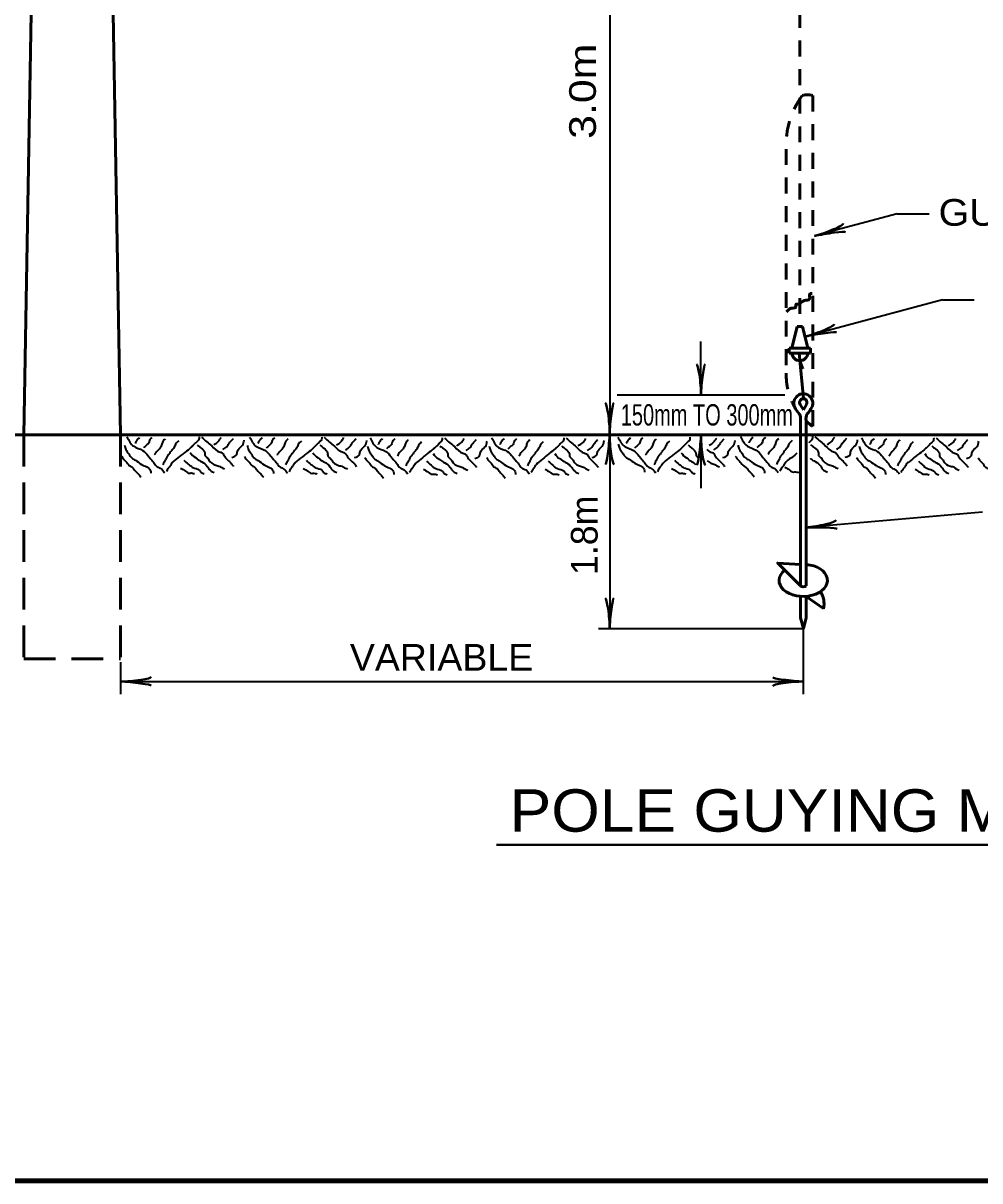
# Model space of a CAD drawing. Extents: x -34 to 821, y -14 to 530.
# Drawn here: x 373.2 to 481.5, y -2.2 to 128.9 of the extents above; entities that cross this region are included whole.
import ezdxf
from ezdxf.enums import TextEntityAlignment as Align

# ---------------------------------------------------------------- set-up
doc = ezdxf.new("R2010")
doc.units = 0
doc.header["$LTSCALE"] = 1.2
doc.linetypes.add('MEDIUM_DASHED', pattern=[4.5, 3, -1.5])
doc.linetypes.add('SHORT_DASHED', pattern=[2.7, 1.5, -1.2])
doc.layers.add('1', color=7, linetype='Continuous', lineweight=53)

msp = doc.modelspace()

# ---------------------------------------------------------------- linework, layer by layer
at = {"layer": '1'}
for p, q in [((376.295, 257.658), (373.223, 82.29)), ((382.823, 159.642), (384.191, 82.29)), ((460.223, 92.106), (460.823, 94.53)), ((460.823, 94.53), (461.423, 94.53)), ((462.023, 92.106), (461.423, 94.53)), ((462.335, 92.106), (459.911, 92.106)), ((459.911, 91.506), (459.911, 92.106)), ((462.335, 91.506), (462.335, 92.106)), ((462.335, 91.506), (459.911, 91.506)), ((461.519, 86.37), (461.063, 91.506)), ((461.135, 90.666), (461.471, 89.754)), ((461.519, 85.098), (461.159, 85.722)), ((461.519, 85.098), (461.879, 85.722)), ((461.831, 83.898), (461.831, 77.562)), ((355.079, 82.29), (581.063, 82.29)), ((461.831, 77.514), (461.831, 65.178)), ((461.831, 63.978), (461.831, 61.554)), ((461.831, 63.978), (463.799, 62.586))]:
    msp.add_line(p, q, dxfattribs=at)
at = {"layer": '1', "linetype": 'SHORT_DASHED'}
for p, q in [((461.135, 162.57), (461.135, 94.53)), ((462.599, 120.69), (462.599, 83.202)), ((459.575, 114.642), (459.575, 89.25))]:
    msp.add_line(p, q, dxfattribs=at)
at = {"layer": '1', "lineweight": 35}
for p, q in [((472.151, 107.298), (462.791, 104.802)), ((472.151, 107.298), (475.775, 107.298)), ((477.263, 97.554), (461.807, 93.402)), ((477.263, 97.554), (480.863, 97.554)), ((449.927, 86.778), (449.927, 92.826)), ((459.431, 86.778), (440.423, 86.778)), ((449.927, 82.29), (449.927, 76.242)), ((481.823, 73.53), (461.831, 71.778)), ((461.495, 60.282), (438.311, 60.282)), ((461.495, 60.234), (461.495, 52.89)), ((384.191, 56.538), (384.191, 52.89)), ((384.191, 54.33), (461.519, 54.33))]:
    msp.add_line(p, q, dxfattribs=at)
at = {"layer": '1', "linetype": 'MEDIUM_DASHED'}
for p, q in [((373.223, 82.29), (373.223, 56.898)), ((384.191, 82.29), (384.191, 56.898)), ((373.223, 56.898), (384.191, 56.898))]:
    msp.add_line(p, q, dxfattribs=at)
at = {"layer": '1', "lineweight": 40}
msp.add_line((426.765, 35.847), (516.827, 35.847), dxfattribs=at)
at = {"layer": '1', "lineweight": 158}
msp.add_line((814.88, -2.224), (23.28, -2.224), dxfattribs=at)
at = {"layer": '1', "lineweight": 35}
msp.add_lwpolyline([(439.583, 161.946), (439.583, 82.41), (439.583, 60.282)], dxfattribs=at)
at = {"layer": '1'}
for points in [[(461.183, 83.898), (461.183, 77.514), (461.183, 65.178)], [(461.183, 65.178), (458.615, 67.746), (461.183, 67.578)], [(461.183, 63.978), (461.183, 61.554), (461.519, 60.33), (461.831, 61.554)]]:
    msp.add_lwpolyline(points, dxfattribs=at)
at = {"layer": '1', "linetype": 'SHORT_DASHED'}
for centre, radius, start, end in [((468.928, 115.142), 9.358, 143.58388, 183.01714), ((462.002, 118.925), 1.872, 71.15616, 108.84384), ((466.628, 88.991), 7.05, 177.90975, 209.56823), ((466.628, 88.991), 7.05, 227.0576, 235.22035)]:
    msp.add_arc(centre, radius, start, end, dxfattribs=at)
at = {"layer": '1'}
for centre, radius, start, end in [((461.127, 91.587), 0.911, 185.20411, 354.79589), ((461.515, 85.848), 1.073, 337.37581, 202.62419), ((463.5, 86.935), 3.332, 206.74116, 223.96028), ((461.514, 85.935), 0.423, 328.9871, 211.0129), ((459.993, 86.634), 2.783, 313.69833, 334.49446), ((459.422, 84.043), 1.777, 355.24577, 19.00426), ((463.596, 84.043), 1.777, 160.99574, 184.75423), ((461.509, 65.52), 0.464, 227.04039, 312.95961), ((461.341, 63.13), 2.526, 347.48706, 33.42981)]:
    msp.add_arc(centre, radius, start, end, dxfattribs=at)
at = {"layer": '1', "lineweight": 40}
for centre, major_axis, ratio, start_param, end_param in [((463.982, 105.454), (-2.038, -0.741), 0.122415, 0.8963533, 3.1415927), ((464.169, 104.893), (2.107, 0.345), 0.07063, 6.2823074, 8.5597026), ((462.984, 94.078), (-2.038, -0.741), 0.122415, 0.8963533, 3.1415927), ((463.171, 93.517), (2.107, 0.345), 0.07063, 6.2823074, 8.5597026), ((449.59, 88.099), (0.189, -2.16), 0.122415, 0.8963533, 3.1415927), ((450.18, 88.134), (0.212, 2.125), 0.07063, 6.2823074, 8.5597026), ((439.245, 83.722), (0.189, -2.16), 0.122415, 0.8963533, 3.1415927), ((439.835, 83.757), (0.212, 2.125), 0.07063, 6.2823074, 8.5597026), ((439.323, 81.047), (-0.212, -2.125), 0.07063, 6.2823074, 8.5597026), ((439.323, 81.047), (-0.212, -2.125), 0.07063, 6.2823074, 8.5597026), ((439.913, 81.082), (-0.189, 2.16), 0.122415, 0.8963533, 3.1415927), ((439.913, 81.082), (-0.189, 2.16), 0.122415, 0.8963533, 3.1415927), ((449.668, 80.944), (-0.212, -2.125), 0.07063, 6.2823074, 8.5597026), ((450.259, 80.98), (-0.189, 2.16), 0.122415, 0.8963533, 3.1415927), ((463.111, 72.226), (-2.135, -0.376), 0.122415, 0.8963533, 3.1415927), ((463.198, 71.641), (2.135, -0.027), 0.07063, 6.2823074, 8.5597026), ((439.245, 61.604), (0.189, -2.16), 0.122415, 0.8963533, 3.1415927), ((439.835, 61.639), (-0.212, -2.125), 0.07063, 3.1407148, 5.41811), ((385.541, 54.076), (-2.125, 0.212), 0.07063, 3.1407148, 5.41811), ((385.506, 54.666), (-2.16, -0.189), 0.122415, 0.8963533, 3.1415927), ((460.208, 53.998), (2.16, 0.189), 0.122415, 0.8963533, 3.1415927), ((460.172, 54.588), (-2.125, 0.212), 0.07063, 6.2823074, 8.5597026)]:
    msp.add_ellipse(centre, major_axis=major_axis, ratio=ratio, start_param=start_param, end_param=end_param, dxfattribs=at)
at = {"layer": '1'}
msp.add_ellipse((461.509, 65.785), major_axis=(-2.736, 0), ratio=0.663245, start_param=5.5824837, end_param=10.8796755, dxfattribs=at)
msp.add_spline([(462.527, 98.274), (462.311, 98.274), (462.239, 97.842), (462.191, 97.602), (461.783, 97.506), (461.303, 97.266), (461.111, 97.098), (460.679, 97.05), (460.655, 96.738), (460.247, 96.618), (459.911, 96.498), (459.623, 96.186)], degree=3, dxfattribs=at)
at = {"layer": '1', "lineweight": 35}
for points in [[(384.911, 82.05), (385.679, 80.97), (386.687, 80.514), (387.311, 79.89), (387.623, 79.506), (388.007, 79.05), (388.319, 78.666), (388.775, 78.426), (389.159, 77.97)], [(386.303, 81.978), (386.183, 81.81), (386.159, 81.81), (386.087, 81.738), (385.871, 81.402), (385.847, 81.306)], [(387.743, 81.93), (387.503, 81.738), (387.431, 81.546), (387.359, 81.306), (387.191, 81.162), (387.119, 81.09), (386.783, 80.802)], [(389.255, 81.81), (389.015, 81.594), (388.871, 81.21), (388.679, 80.826), (388.247, 80.346), (388.079, 80.106), (388.007, 80.01)], [(390.767, 81.594), (390.407, 81.21), (390.215, 80.778), (389.903, 80.418), (389.663, 80.082), (389.447, 79.818), (389.327, 79.53), (389.159, 79.266), (388.967, 78.882)], [(393.071, 82.05), (393.071, 81.906), (392.999, 81.666), (392.855, 81.522), (392.687, 81.354), (392.375, 81.066), (392.159, 80.826), (391.463, 80.274), (391.055, 79.962), (390.287, 79.362), (389.975, 79.05), (389.831, 78.81), (389.591, 78.498), (389.375, 78.114)], [(393.359, 82.026), (393.959, 81.474), (394.511, 81.018), (395.447, 80.322), (395.663, 80.25), (395.903, 79.938), (396.287, 79.458), (396.743, 79.002), (396.983, 78.69)], [(394.751, 81.162), (395.279, 81.546), (395.399, 81.714), (395.591, 81.978)], [(395.783, 80.61), (396.215, 80.922), (396.479, 81.306), (396.551, 81.426), (396.719, 81.594), (396.959, 81.858)], [(396.791, 79.722), (397.343, 80.034), (397.415, 80.394), (397.919, 81.018), (398.063, 81.21), (398.159, 81.522), (398.183, 81.666)], [(398.807, 82.026), (399.575, 80.946), (400.583, 80.49), (401.207, 79.866), (401.519, 79.482), (401.903, 79.026), (402.215, 78.642), (402.671, 78.402), (403.079, 77.946)], [(400.199, 81.954), (400.079, 81.786), (400.055, 81.786), (399.983, 81.714), (399.767, 81.378), (399.743, 81.282)], [(401.639, 81.906), (401.399, 81.714), (401.327, 81.522), (401.255, 81.282), (401.087, 81.138), (401.015, 81.066), (400.679, 80.778)], [(403.151, 81.786), (402.911, 81.57), (402.767, 81.186), (402.575, 80.778), (402.143, 80.322), (401.975, 80.082), (401.903, 79.986)], [(404.663, 81.57), (404.303, 81.186), (404.111, 80.754), (403.799, 80.394), (403.559, 80.058), (403.343, 79.794), (403.223, 79.506), (403.079, 79.242), (402.863, 78.858)], [(406.967, 82.026), (406.967, 81.882), (406.895, 81.642), (406.751, 81.498), (406.583, 81.33), (406.271, 81.042), (406.055, 80.802), (405.359, 80.25), (404.975, 79.938), (404.183, 79.338), (403.871, 79.026), (403.727, 78.786), (403.487, 78.474), (403.271, 78.09)], [(407.255, 82.002), (407.855, 81.45), (408.407, 80.994), (409.343, 80.298), (409.559, 80.226), (409.799, 79.914), (410.183, 79.434), (410.663, 78.978), (410.879, 78.666)], [(408.647, 81.138), (409.175, 81.522), (409.295, 81.69), (409.487, 81.954)], [(409.679, 80.586), (410.111, 80.898), (410.375, 81.282), (410.447, 81.402), (410.615, 81.57), (410.855, 81.834)], [(410.687, 79.698), (411.239, 80.01), (411.311, 80.37), (411.815, 80.994), (411.959, 81.186), (412.055, 81.474), (412.079, 81.642)], [(412.439, 81.93), (413.207, 80.85), (414.215, 80.394), (414.839, 79.77), (415.151, 79.386), (415.535, 78.93), (415.847, 78.522), (416.303, 78.306), (416.687, 77.826)], [(413.831, 81.858), (413.711, 81.69), (413.663, 81.69), (413.591, 81.618), (413.399, 81.258), (413.351, 81.186)], [(415.247, 81.81), (415.031, 81.618), (414.959, 81.426), (414.863, 81.186), (414.719, 81.042), (414.647, 80.97), (414.287, 80.682)], [(416.759, 81.69), (416.543, 81.474), (416.375, 81.066), (416.183, 80.682), (415.751, 80.226), (415.607, 79.986), (415.535, 79.866)], [(418.271, 81.474), (417.935, 81.066), (417.743, 80.658), (417.431, 80.298), (417.191, 79.962), (416.951, 79.674), (416.855, 79.41), (416.687, 79.146), (416.495, 78.762)], [(420.599, 81.93), (420.599, 81.786), (420.527, 81.546), (420.359, 81.402), (420.215, 81.234), (419.903, 80.922), (419.663, 80.706), (418.967, 80.154), (418.583, 79.842), (417.815, 79.218), (417.503, 78.93), (417.359, 78.69), (417.119, 78.378), (416.879, 77.994)], [(420.863, 81.906), (421.487, 81.354), (422.039, 80.898), (422.951, 80.202), (423.191, 80.13), (423.431, 79.818), (423.815, 79.338), (424.271, 78.882), (424.511, 78.57)], [(422.255, 81.042), (422.807, 81.426), (422.927, 81.57), (423.119, 81.858)], [(423.311, 80.49), (423.743, 80.802), (424.007, 81.186), (424.079, 81.306), (424.247, 81.474), (424.463, 81.738)], [(424.319, 79.602), (424.847, 79.914), (424.943, 80.274), (425.423, 80.874), (425.591, 81.066), (425.663, 81.378), (425.711, 81.546)], [(426.215, 81.93), (426.983, 80.85), (427.991, 80.394), (428.615, 79.77), (428.903, 79.386), (429.311, 78.93), (429.599, 78.522), (430.079, 78.306), (430.463, 77.826)], [(427.607, 81.858), (427.487, 81.69), (427.439, 81.69), (427.367, 81.618), (427.175, 81.258), (427.127, 81.186)], [(429.023, 81.81), (428.807, 81.618), (428.711, 81.426), (428.639, 81.186), (428.495, 81.042), (428.399, 80.97), (428.063, 80.682)], [(430.535, 81.69), (430.295, 81.474), (430.151, 81.066), (429.959, 80.682), (429.527, 80.226), (429.383, 79.986), (429.311, 79.866)], [(432.047, 81.474), (431.711, 81.066), (431.495, 80.658), (431.207, 80.298), (430.967, 79.962), (430.727, 79.674), (430.607, 79.41), (430.463, 79.146), (430.271, 78.762)], [(434.375, 81.93), (434.375, 81.786), (434.303, 81.546), (434.135, 81.402), (433.991, 81.234), (433.679, 80.922), (433.439, 80.706), (432.743, 80.154), (432.359, 79.842), (431.591, 79.218), (431.279, 78.93), (431.111, 78.69), (430.895, 78.378), (430.655, 77.994)], [(434.639, 81.906), (435.263, 81.354), (435.791, 80.898), (436.727, 80.202), (436.967, 80.13), (437.183, 79.818), (437.591, 79.338), (438.047, 78.882), (438.287, 78.57)], [(436.031, 81.042), (436.583, 81.426), (436.703, 81.57), (436.895, 81.858)], [(437.087, 80.49), (437.495, 80.802), (437.783, 81.186), (437.855, 81.306), (437.999, 81.474), (438.239, 81.738)], [(437.591, 79.698), (438.119, 80.01), (438.215, 80.37), (438.719, 80.994), (438.863, 81.186), (438.935, 81.474), (438.983, 81.642)], [(440.519, 82.026), (441.311, 80.946), (442.295, 80.49), (442.919, 79.866), (443.231, 79.482), (443.615, 79.026), (443.927, 78.642), (444.407, 78.402), (444.791, 77.946)], [(441.911, 81.954), (441.815, 81.786), (441.767, 81.786), (441.695, 81.714), (441.503, 81.378), (441.455, 81.282)], [(443.351, 81.906), (443.111, 81.714), (443.039, 81.522), (442.967, 81.282), (442.799, 81.138), (442.727, 81.066), (442.391, 80.778)], [(444.863, 81.786), (444.623, 81.57), (444.479, 81.186), (444.287, 80.778), (443.855, 80.322), (443.711, 80.082), (443.615, 79.986)], [(446.375, 81.57), (446.015, 81.186), (445.823, 80.754), (445.511, 80.394), (445.295, 80.058), (445.055, 79.794), (444.935, 79.506), (444.791, 79.242), (444.599, 78.858)], [(448.679, 82.026), (448.679, 81.882), (448.607, 81.642), (448.463, 81.498), (448.295, 81.33), (447.983, 81.042), (447.767, 80.802), (447.071, 80.25), (446.687, 79.938), (445.895, 79.338), (445.607, 79.026), (445.439, 78.786), (445.199, 78.474), (444.983, 78.09)], [(450.863, 81.09), (451.391, 81.474), (451.511, 81.618), (451.703, 81.906)], [(451.391, 80.586), (451.823, 80.898), (452.087, 81.282), (452.183, 81.402), (452.327, 81.57), (452.567, 81.834)], [(452.399, 79.698), (452.951, 80.01), (453.023, 80.37), (453.527, 80.994), (453.671, 81.186), (453.767, 81.474), (453.791, 81.642)], [(454.391, 82.098), (455.183, 80.994), (456.167, 80.538), (456.791, 79.914), (457.103, 79.53), (457.487, 79.074), (457.799, 78.69), (458.279, 78.45), (458.663, 77.994)], [(455.783, 82.002), (455.663, 81.834), (455.639, 81.834), (455.567, 81.762), (455.375, 81.426), (455.327, 81.354)], [(457.223, 81.954), (456.983, 81.762), (456.911, 81.57), (456.839, 81.354), (456.671, 81.186), (456.599, 81.114), (456.263, 80.85)], [(458.735, 81.834), (458.495, 81.618), (458.351, 81.234), (458.159, 80.85), (457.727, 80.37), (457.559, 80.154), (457.487, 80.034)], [(460.247, 81.618), (459.887, 81.234), (459.695, 80.802), (459.383, 80.442), (459.167, 80.106), (458.927, 79.842), (458.807, 79.554), (458.663, 79.29), (458.471, 78.906)], [(462.551, 82.098), (462.551, 81.93), (462.479, 81.69), (462.335, 81.546), (462.167, 81.402), (462.143, 81.354)], [(462.839, 82.05), (463.463, 81.498), (463.991, 81.042), (464.927, 80.346), (465.143, 80.274), (465.383, 79.962), (465.767, 79.506), (466.247, 79.026), (466.463, 78.714)], [(464.231, 81.186), (464.759, 81.57), (464.879, 81.738), (465.071, 82.002)], [(465.263, 80.634), (465.695, 80.946), (465.959, 81.354), (466.055, 81.45), (466.199, 81.618), (466.439, 81.882)], [(466.271, 79.746), (466.823, 80.058), (466.895, 80.418), (467.399, 81.042), (467.543, 81.234), (467.639, 81.546), (467.663, 81.69)], [(468.119, 81.93), (468.887, 80.85), (469.895, 80.394), (470.519, 79.77), (470.831, 79.386), (471.215, 78.93), (471.527, 78.522), (471.983, 78.306), (472.367, 77.826)], [(469.511, 81.858), (469.391, 81.69), (469.367, 81.69), (469.271, 81.618), (469.079, 81.258), (469.055, 81.186)], [(470.951, 81.81), (470.711, 81.618), (470.639, 81.426), (470.567, 81.186), (470.399, 81.042), (470.327, 80.97), (469.967, 80.682)], [(472.463, 81.69), (472.223, 81.474), (472.055, 81.066), (471.863, 80.682), (471.455, 80.226), (471.287, 79.986), (471.215, 79.866)], [(473.951, 81.474), (473.615, 81.066), (473.423, 80.658), (473.111, 80.298), (472.871, 79.962), (472.655, 79.674), (472.535, 79.41), (472.367, 79.146), (472.175, 78.762)], [(476.279, 81.93), (476.279, 81.786), (476.207, 81.546), (476.063, 81.402), (475.895, 81.234), (475.583, 80.922), (475.367, 80.706), (474.671, 80.154), (474.263, 79.842), (473.495, 79.218), (473.183, 78.93), (473.039, 78.69), (472.799, 78.378), (472.559, 77.994)], [(476.567, 81.906), (477.167, 81.354), (477.719, 80.898), (478.655, 80.202), (478.871, 80.13), (479.111, 79.818), (479.495, 79.338), (479.951, 78.882), (480.191, 78.57)], [(477.959, 81.042), (478.487, 81.426), (478.607, 81.57), (478.799, 81.858)], [(478.991, 80.49), (479.423, 80.802), (479.687, 81.186), (479.759, 81.306), (479.927, 81.474), (480.143, 81.738)], [(479.999, 79.602), (480.551, 79.914), (480.623, 80.274), (481.127, 80.874), (481.271, 81.066), (481.343, 81.378), (481.391, 81.546)], [(384.647, 81.09), (384.791, 80.61), (385.103, 80.106), (385.487, 79.626), (385.871, 79.386), (386.543, 78.93), (387.575, 78.21), (387.623, 77.922)], [(392.063, 80.274), (392.663, 79.698), (392.759, 79.65), (392.879, 79.53), (393.383, 79.218), (394.007, 78.69), (394.199, 78.378), (394.775, 78.018)], [(392.855, 81.114), (393.071, 80.97), (393.311, 80.778), (393.743, 80.226), (393.767, 79.89), (394.079, 79.626), (394.199, 79.41), (394.967, 78.834), (395.447, 78.69), (395.567, 78.618), (395.975, 78.426)], [(398.543, 81.066), (398.687, 80.586), (398.999, 80.082), (399.383, 79.578), (399.767, 79.362), (400.439, 78.882), (401.471, 78.186), (401.519, 77.898)], [(405.959, 80.25), (406.559, 79.674), (406.655, 79.626), (406.775, 79.506), (407.279, 79.194), (407.903, 78.666), (408.095, 78.354), (408.671, 77.994)], [(406.751, 81.09), (406.967, 80.946), (407.207, 80.754), (407.639, 80.202), (407.663, 79.866), (407.975, 79.578), (408.095, 79.386), (408.863, 78.81), (409.343, 78.666), (409.463, 78.594), (409.871, 78.402)], [(412.151, 80.97), (412.319, 80.49), (412.631, 79.986), (413.015, 79.482), (413.399, 79.266), (414.047, 78.786), (415.103, 78.09), (415.151, 77.778)], [(419.591, 80.154), (420.167, 79.578), (420.287, 79.53), (420.407, 79.41), (420.911, 79.098), (421.535, 78.57), (421.727, 78.258), (422.303, 77.898)], [(420.359, 80.994), (420.599, 80.85), (420.839, 80.658), (421.247, 80.106), (421.295, 79.77), (421.607, 79.482), (421.727, 79.29), (422.495, 78.714), (422.951, 78.57), (423.071, 78.474), (423.503, 78.282)], [(425.927, 80.97), (426.095, 80.49), (426.407, 79.986), (426.791, 79.482), (427.175, 79.266), (427.823, 78.786), (428.879, 78.09), (428.903, 77.778)], [(433.367, 80.154), (433.943, 79.578), (434.063, 79.53), (434.183, 79.41), (434.687, 79.098), (435.287, 78.57), (435.503, 78.258), (436.079, 77.898)], [(434.135, 80.994), (434.375, 80.85), (434.591, 80.658), (435.023, 80.106), (435.071, 79.77), (435.383, 79.482), (435.503, 79.29), (436.271, 78.714), (436.727, 78.57), (436.847, 78.474), (437.279, 78.282)], [(440.543, 81.21), (440.711, 80.754), (441.023, 80.25), (441.407, 79.746), (441.791, 79.506), (442.439, 79.05), (443.495, 78.354), (443.543, 78.042)], [(447.695, 80.25), (448.271, 79.674), (448.391, 79.626), (448.487, 79.506), (448.991, 79.194), (449.303, 78.93)], [(448.463, 81.09), (448.679, 80.946), (448.919, 80.754), (449.351, 80.202), (449.399, 79.866), (449.591, 79.674)], [(450.623, 80.634), (451.055, 80.298), (451.295, 80.226), (451.511, 79.914), (451.895, 79.434), (452.375, 78.978), (452.591, 78.666)], [(454.127, 81.114), (454.271, 80.634), (454.583, 80.154), (454.967, 79.65), (455.375, 79.41), (456.023, 78.954), (457.079, 78.258), (457.103, 77.946)], [(460.775, 80.178), (460.559, 79.986), (459.767, 79.386), (459.455, 79.074), (459.311, 78.834), (459.071, 78.522), (458.855, 78.138)], [(462.335, 81.138), (462.551, 80.994), (462.791, 80.802), (463.223, 80.25), (463.247, 79.914), (463.559, 79.65), (463.679, 79.458), (464.447, 78.858), (464.927, 78.714), (465.047, 78.642), (465.455, 78.45)], [(467.855, 80.97), (467.999, 80.49), (468.311, 79.986), (468.695, 79.482), (469.079, 79.266), (469.751, 78.786), (470.783, 78.09), (470.831, 77.778)], [(475.271, 80.154), (475.847, 79.578), (475.967, 79.53), (476.087, 79.41), (476.591, 79.098), (477.215, 78.57), (477.407, 78.258), (477.983, 77.898)], [(476.063, 80.994), (476.279, 80.85), (476.519, 80.658), (476.951, 80.106), (476.975, 79.77), (477.287, 79.482), (477.407, 79.29), (478.175, 78.714), (478.655, 78.57), (478.751, 78.474), (479.183, 78.282)], [(384.335, 79.842), (384.479, 79.578), (384.791, 79.266), (385.175, 78.81), (385.535, 78.57), (385.847, 78.186), (386.159, 77.874), (386.471, 77.49)], [(391.343, 79.41), (391.847, 78.954), (392.039, 78.81), (392.375, 78.57), (393.071, 78.306), (393.311, 78.018), (393.671, 77.874)], [(398.231, 79.818), (398.375, 79.554), (398.687, 79.242), (399.071, 78.786), (399.431, 78.546), (399.743, 78.162), (400.055, 77.85), (400.367, 77.466)], [(405.239, 79.386), (405.743, 78.93), (405.935, 78.786), (406.271, 78.546), (406.967, 78.282), (407.207, 77.994), (407.567, 77.85)], [(411.863, 79.722), (412.007, 79.458), (412.319, 79.146), (412.703, 78.666), (413.063, 78.45), (413.351, 78.066), (413.663, 77.754), (413.975, 77.37)], [(418.847, 79.29), (419.351, 78.834), (419.543, 78.666), (419.903, 78.45), (420.599, 78.186), (420.839, 77.898), (421.175, 77.754)], [(425.615, 79.722), (425.783, 79.458), (426.095, 79.146), (426.479, 78.666), (426.815, 78.45), (427.127, 78.066), (427.439, 77.754), (427.751, 77.37)], [(432.623, 79.29), (433.127, 78.834), (433.319, 78.666), (433.679, 78.45), (434.375, 78.186), (434.591, 77.898), (434.951, 77.754)], [(446.951, 79.386), (447.455, 78.93), (447.647, 78.786), (447.983, 78.546), (448.679, 78.282), (448.919, 77.994), (449.279, 77.85)], [(450.623, 79.362), (451.031, 79.074), (451.511, 78.906), (451.607, 78.834), (452.039, 78.642)], [(453.815, 79.866), (453.983, 79.602), (454.271, 79.29), (454.679, 78.834), (455.015, 78.594), (455.327, 78.21), (455.639, 77.898), (455.951, 77.514)], [(462.335, 79.578), (462.359, 79.554), (462.863, 79.242), (463.487, 78.714), (463.679, 78.402), (464.255, 78.042)], [(467.543, 79.722), (467.687, 79.458), (467.999, 79.146), (468.383, 78.666), (468.743, 78.45), (469.055, 78.066), (469.367, 77.754), (469.679, 77.37)], [(474.551, 79.29), (475.055, 78.834), (475.247, 78.666), (475.583, 78.45), (476.279, 78.186), (476.519, 77.898), (476.855, 77.754)], [(481.319, 79.674), (481.463, 79.41), (481.775, 79.098), (482.159, 78.618), (482.519, 78.402), (482.831, 78.018), (483.119, 77.706), (483.431, 77.322)], [(390.983, 78.498), (391.271, 78.33), (391.775, 77.994), (391.847, 77.946), (392.063, 77.946), (392.567, 77.874)], [(404.879, 78.474), (405.167, 78.306), (405.671, 77.97), (405.743, 77.922), (405.959, 77.922), (406.463, 77.85)], [(418.511, 78.378), (418.775, 78.21), (419.279, 77.874), (419.351, 77.826), (419.591, 77.826), (420.095, 77.754)], [(432.287, 78.378), (432.551, 78.21), (433.055, 77.874), (433.127, 77.826), (433.367, 77.826), (433.871, 77.754)], [(446.591, 78.474), (446.879, 78.306), (447.383, 77.97), (447.455, 77.922), (447.695, 77.922), (448.199, 77.85)], [(459.431, 78.618), (459.695, 78.474), (460.199, 78.114), (460.271, 78.066), (460.511, 78.066), (461.015, 77.994)], [(474.191, 78.378), (474.455, 78.21), (474.959, 77.874), (475.055, 77.826), (475.271, 77.826), (475.775, 77.754)]]:
    msp.add_spline(points, degree=3, dxfattribs=at)

# ---------------------------------------------------------------- texts
at = {"layer": '1', "width": 1.2}
msp.add_text('3.0m', height=3.024, rotation=90, dxfattribs=at).set_placement((438.023, 121.187), align=Align.CENTER)
at = {"layer": '1'}
for s, height, width, p in [('GUY GUARD', 3.024, 1.1, (490.309, 105.954)), ('150mm TO 300mm', 2.419, 0.7, (450.592, 83.325)), ('VARIABLE', 3.024, 1.05, (420.541, 55.554))]:
    msp.add_text(s, height=height, dxfattribs=dict(at, width=width)).set_placement(p, align=Align.CENTER)
msp.add_text('1.8m', height=3.024, rotation=90, dxfattribs=at).set_placement((438.215, 70.89), align=Align.CENTER)
at = {"layer": '1', "width": 1.1}
msp.add_text('POLE GUYING METHODS', height=4.8, dxfattribs=at).set_placement((428.261, 37.322))

doc.saveas('drawing.dxf')
